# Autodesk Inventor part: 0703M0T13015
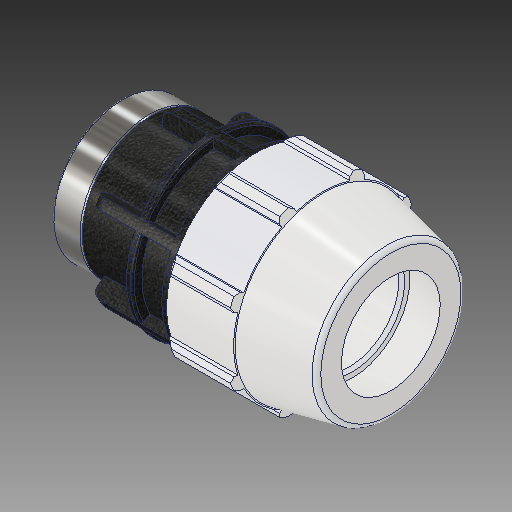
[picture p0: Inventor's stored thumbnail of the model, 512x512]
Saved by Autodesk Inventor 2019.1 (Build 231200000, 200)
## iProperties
Created: 2017-02
Part Number: 0703M0T13015
Material: PVC-Piping
Description: PLASSON FEMALE ADAPTOR G 1 1/4'' - 1 1/2''F
Document SubType Name: Modeling
Designer: KIM
Mass: 92.6774 g
Surface Area: 199.44 cm^2
Volume: 66.1981 cm^3
Density: 1.4 g/cm^3
Appearance: PTFE
Author: KIM
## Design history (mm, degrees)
derived "0703M0T.ipt"
feature "Solid1::0703M0T.ipt"
tag "TaggingFeature1"
body "Solid1"
other parameters: "d2" = 42.1, "d4" = 16.43743, "d5" = 28.7655, "d7" = 82.042, "d9" = 16.43743, "d11" = 3.28749, "d12" = 65.6336, "d13" = 120 deg, "d14" = 63.15, "d15" = 12 deg, "d16" = 73.8378, "d18" = 2.105, "d19" = 35 deg, "d20" = 17.5 deg, "d21" = 76.29906, "d23" = 0, "d25" = 360 deg, "d27" = 1.64084, "d34" = 4.1021, "d35" = 34.5186, "d36" = 0, "d42" = 28.7655, "d43" = 2.46126, "d46" = 1.263, "d49" = 85.09, "d51" = 115.062, "d53" = 0.842, "d55" = 360 deg, "d61" = 24.892, "d62" = 39.995, "d63" = 44.845, "d64" = 38.354, "d65" = 4.1021, "d66" = 0.5, "d67" = 1, "d68" = 12.446, "d69" = 59.07024, "d70" = 1.27, "d_" = 42.1, "E_" = 82.042, "H_" = 115.062, "l_" = 85.09, "l_2" = 24.892, "G_" = 44.845
